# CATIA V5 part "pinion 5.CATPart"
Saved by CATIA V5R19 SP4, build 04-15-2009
Part number: pinion 5
Bounding box of the stored display mesh (mm): x 0 to 22.15, y -24.146 to 24.146, z -23.97 to 23.97
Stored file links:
  G:\EU_thinkMotion\CFAO_2010\MMS_groupe1\MMS_groupe1\A reprendre\OK\rdeneffle\pinion 5.CATPart
  G:\EU_thinkMotion\CFAO_2010\MMS_groupe1\MMS_groupe1\A reprendre\OK\rdeneffle\pinion 2.CATPart
  G:\EU_thinkMotion\CFAO_2010\MMS_groupe1\MMS_groupe1\A reprendre\OK\rdeneffle\systeme d'ouverture de porte de voiture.CATProduct
  G:\EU_thinkMotion\CFAO_2010\MMS_groupe1\MMS_groupe1\A reprendre\OK\rdeneffle\piece gauche carter.CATPart
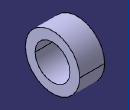
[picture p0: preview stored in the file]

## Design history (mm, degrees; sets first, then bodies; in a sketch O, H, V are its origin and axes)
Parameters
  `rayon interieur.1` = 15.505 mm
  `rayon extérieur.1` = 24.146 mm
Body1 (main body)
Body2
  Sketch1 on yz-plane, origin (0, 0, 0), H (0, 1, 0), V (0, 0, 1)
    circle A1 centre (0, 0) radius 15.505
    circle A2 centre (0, 0) radius 24.146
    radius A2 = 24.146 {= `rayon extérieur.1`}
    radius A1 = 15.505 {= `rayon interieur.1`}
  Pad1: profile Sketch1, direction (1, 0, 0), length 22.15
